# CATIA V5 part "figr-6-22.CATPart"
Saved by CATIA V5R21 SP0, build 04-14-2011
Part number: Part1
Bounding box of the stored display mesh (mm): x 0 to 150, y -70 to 70, z -150 to 69.804
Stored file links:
  D:\CATIA V5R21 E-RESOURCES\CATIA-V5R21\catia-v5r21-prt\c06-catia-v5r21-prt\c06-catia-v5r21-figr-6-22.CATPart
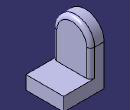
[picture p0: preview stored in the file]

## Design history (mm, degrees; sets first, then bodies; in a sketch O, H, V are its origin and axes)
Body1 (main body)
  Sketch1 on yz-plane, origin (0, 0, 0), H (0, 1, 0), V (0, 0, 1)
    arc A1 centre (0, 0) radius 70 from (70, 0) to (-70, 0) ccw
    point P1 (70, 0)
    point P2 (-70, 0)
    line L1 (-70, 0) -> (-70, -150)
    line L2 (-70, -150) -> (70, -150)
    line L3 (70, -150) -> (70, 0)
    construction circle A2 centre (0, 0) radius 37.5
    radius A1 = 70
    radius A2 = 37.5
    distance O L2 = 150
    coincidence: P1 H, P2 H
    tangency: L1 A1, L3 A1
    horizontal: L2 H
  Pad1: profile Sketch1, direction (1, 0, 0), length 50
  Sketch2 on face of Pad1, origin (50, 0, 0), H (0, 1, 0), V (0, 0, 1)
    line L1 (-70, -150) -> (70, -150)
    line L2 (70, -150) -> (70, -100)
    line L3 (70, -100) -> (-70, -100)
    line L4 (-70, -100) -> (-70, -150)
    reference projected line E1 (-70, -150) -> (70, -150) from edge [face of Pad1 | face of Pad1]
    reference projected line E2 (-70, 0) -> (-70, -150) from edge [face of Pad1 | face of Pad1]
    reference projected line E3 (70, -150) -> (70, 0) from edge [face of Pad1 | face of Pad1]
    length L2 = 50
    horizontal: L1 H, L3 H
    vertical: L2 V, L4 V
    coincidence: L1 E1, E2 L4, L2 E3
  Pad2: profile Sketch2, direction (1, 0, 0), length 100
  Fillet1: radius 15, on edge [face of Pad2 | end face of Pad1]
